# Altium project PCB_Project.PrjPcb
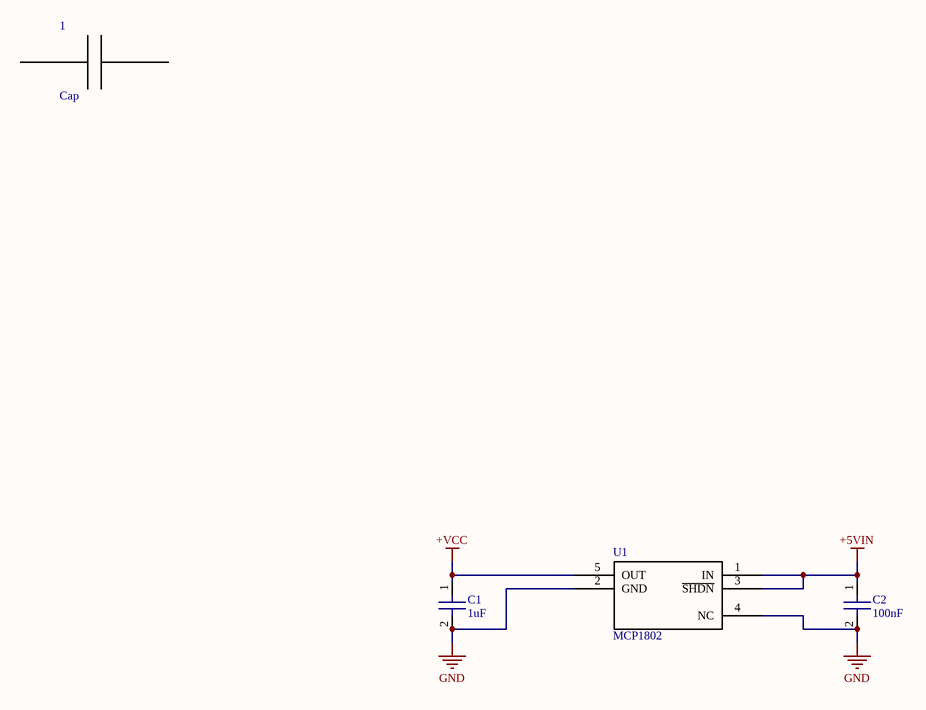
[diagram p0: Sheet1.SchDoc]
1 sheet, 4 parts. Net scope: global (net labels, ports and power ports of the same name join across sheets).
Board file: PCB1.PcbDoc

## Sheet Sheet1.SchDoc
size A4

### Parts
1  Cap
C1  1uF  [CAPC1005X06N]
C2  100nF  [CAPC1005X06N]
U1  MCP1802  [MCP1802_SOT23-5]

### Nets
+5VIN: C2.1 U1.1(IN) U1.3(~{SHDN})
+VCC: C1.1 U1.5(OUT)
GND: C1.2 C2.2 U1.2(GND) U1.4(NC)

Not connected (* = marked no-connect by the designer): 1 ?1 ?2

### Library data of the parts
C1 C2 = Cap
U1 = MCP1802: 300 mA, High PSRR, Low Quiescent Current LDO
